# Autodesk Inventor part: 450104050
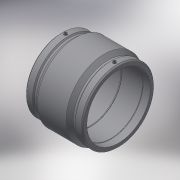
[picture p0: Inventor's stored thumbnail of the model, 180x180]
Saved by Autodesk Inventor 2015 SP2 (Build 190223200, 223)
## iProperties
Created: 2017-06
Part Number: 450104050
Material: Generic
Description: PLASSON COUPLER 50 PN25
Document SubType Name: Modeling
Designer: KIM
Mass: 8622.19 g
Surface Area: 6772.47 cm^2
Volume: 8622.19 cm^3
Density: 1 g/cm^3
Appearance: Default
Author: KIM
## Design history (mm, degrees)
derived "450104.ipt"
feature "Solid1::450104.ipt"
tag "TaggingFeature1"
body "Solid1"
other parameters: "d2" = 68, "d3" = 49, "d4" = 25, "d5" = 61.2, "d8" = 168 deg, "d10" = 19.6, "d11" = 6.53333, "d14" = 17.6296, "d15" = 49, "d16" = 49, "d17" = 49.5, "d19" = 3.52592, "d20" = 168 deg, "d22" = 63.92, "d23" = 68, "d24" = 62.0024, "d25" = 135 deg, "d26" = 45, "d27" = 135 deg, "d29" = 52, "d30" = 15, "d31" = 35, "d34" = 5 deg, "d35" = 15, "d39" = 5 deg, "d41" = 4, "d42" = 14, "d43" = 0, "d45" = 4, "d46" = 14, "d47" = 0, "d48" = 3, "d49" = 0, "d50" = 3, "d51" = 0, "d52" = 14.21, "d53" = 3.5525, "L_1" = 49, "D_" = 68, "A_" = 52, "d_2" = 12
